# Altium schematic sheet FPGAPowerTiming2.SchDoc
size B
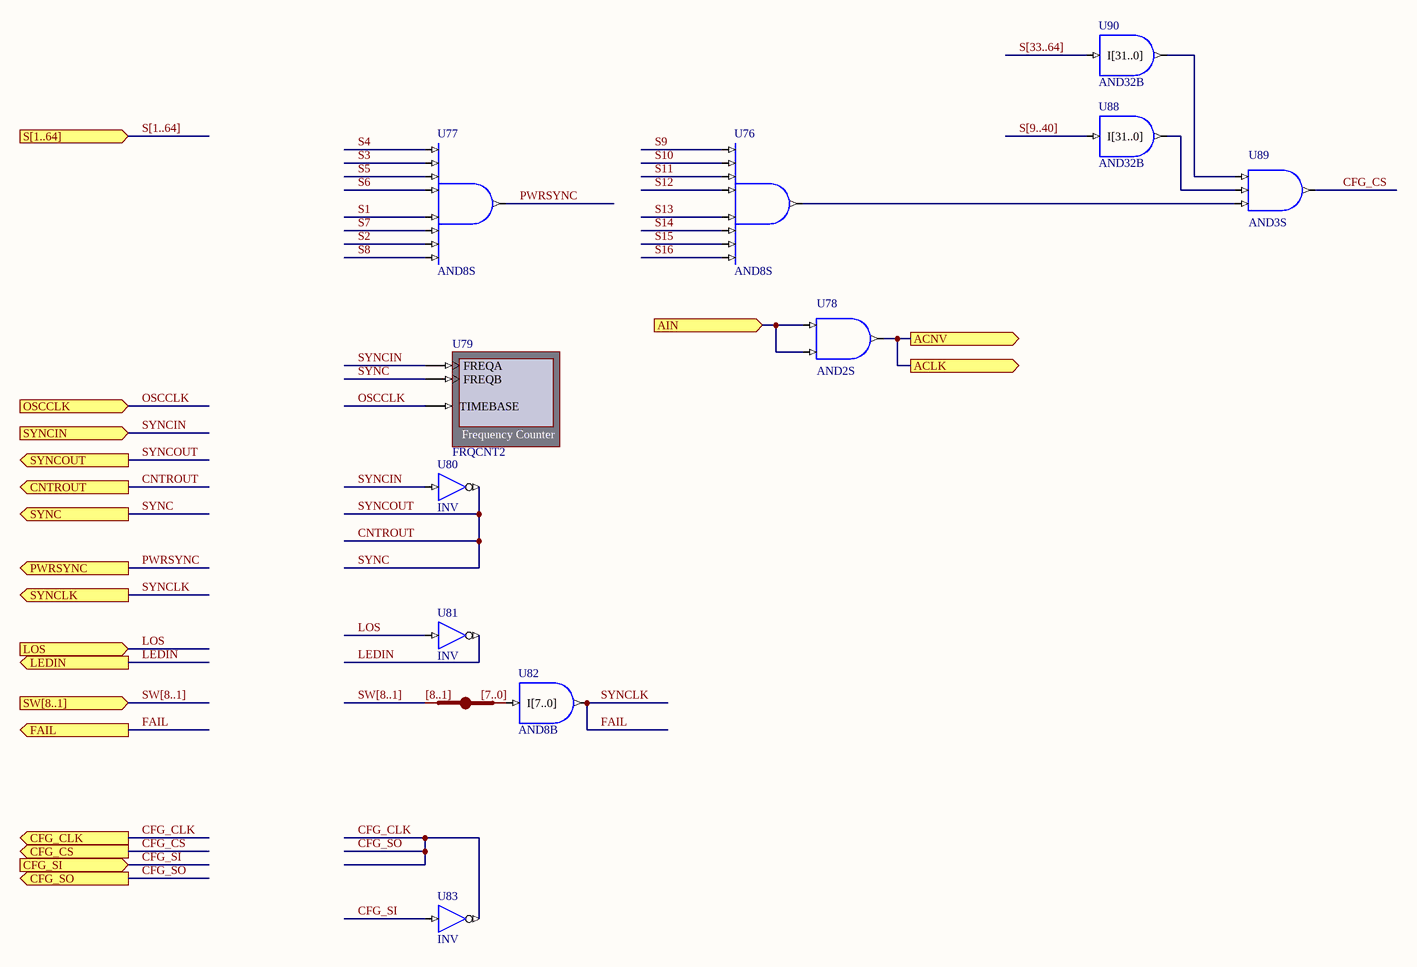
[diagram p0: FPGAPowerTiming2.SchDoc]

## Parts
JB_AUTO?  IndexA: [8..1]  IndexB: [7..0]  (hidden comment: JB)
U76  AND8S
U77  AND8S
U78  AND2S
U79  FRQCNT2
U80  INV
U81  INV
U82  AND8B
U83  INV
U88  AND32B
U89  AND3S
U90  AND32B

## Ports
ACLK (out), ACNV (out), AIN (in), CFG_CLK (out), CFG_CS (out), CFG_SI (in), CFG_SO (out), CNTROUT (out), FAIL (out), LEDIN (out), LOS (in), OSCCLK (in), PWRSYNC (out), S[1..64] (in), SW[8..1] (in), SYNC (out), SYNCIN (in), SYNCLK (out), SYNCOUT (out)

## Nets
ACLK: U78.O ; port ACLK, port ACNV
AIN: U78.I0 U78.I1 ; port AIN
CFG_CLK: U83.O ; port CFG_CLK, port CFG_SO  [also labelled CFG_SO]
CFG_CS: U89.O ; port CFG_CS
CFG_SI: U83.I ; port CFG_SI
CNTROUT: U79.FREQB U80.O ; port SYNCOUT, port CNTROUT, port SYNC  [also labelled SYNC, SYNCOUT]
FAIL: U82.O ; port SYNCLK, port FAIL  [also labelled SYNCLK]
LEDIN: U81.O ; port LEDIN
LOS: U81.I ; port LOS
OSCCLK: U79.TIMEBASE ; port OSCCLK
PWRSYNC: U77.O ; port PWRSYNC
S1: U77.I4
S2: U77.I6
S3: U77.I1
S4: U77.I0
S5: U77.I2
S6: U77.I3
S7: U77.I5
S8: U77.I7
S9: U76.I0
S10: U76.I1
S11: U76.I2
S12: U76.I3
S13: U76.I4
S14: U76.I5
S15: U76.I6
S16: U76.I7
SYNCIN: U79.FREQA U80.I ; port SYNCIN
NetJB_AUTO?_B[0..0]: JB_AUTO?.B[0..0] U82.I[7..0]
NetU76_O: U76.O U89.I2
NetU88_O: U88.O U89.I1
NetU89_I0: U89.I0 U90.O

Not connected (* = marked no-connect by the designer): JB_AUTO? A[0..0]; U88 I[31..0]; U90 I[31..0]

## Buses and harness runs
bus S[1..64] = port S[1..64]
bus S[9..40]
bus S[33..64]
bus SW[8..1]
bus SW[8..1] = port SW[8..1]

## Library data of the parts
JB_AUTO? = JB: System BUS Joiner
U76 U77 = AND8S: 8-Input AND Gate, Single Pin Version; XilinxEquivalent: AND8; FunctionalClass: Logic Primitive; PortSize: 8; ArchiveName: GENERIC; VHDLIB_SIM: GENERIC_LIB
U78 = AND2S: 2-Input AND Gate, Single Pin Version; XilinxEquivalent: AND2; FunctionalClass: Logic Primitive; PortSize: 2; ArchiveName: GENERIC; VHDLIB_SIM: GENERIC_LIB
U79 = FRQCNT2: Frequency Counter; NEXUS_CORE: Instrument; NEXUS_JTAG_DEVICE: True; NEXUS_JTAG_ORDER: 0
U80 U81 U83 = INV: Inverter; FunctionalClass: Logic Primitive; ArchiveName: GENERIC; VHDLIB_SIM: GENERIC_LIB
U82 = AND8B: 8-Input AND Gate, Bus Version; FunctionalClass: Logic Primitive; PortSize: 8; ArchiveName: GENERIC; VHDLIB_SIM: GENERIC_LIB
U88 U90 = AND32B: 32-Input AND Gate, Bus Version; FunctionalClass: Logic Primitive; PortSize: 32; ArchiveName: GENERIC; VHDLIB_SIM: GENERIC_LIB
U89 = AND3S: 3-Input AND Gate, Single Pin Version; XilinxEquivalent: AND3; FunctionalClass: Logic Primitive; PortSize: 3; ArchiveName: GENERIC; VHDLIB_SIM: GENERIC_LIB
